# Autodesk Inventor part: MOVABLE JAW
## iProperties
Created: 2006-07
Part Number: MOVABLE JAW
Material: Cast Iron
Document SubType Name: Modeling
Designer: rollin42
Density: 7.25 g/cm^3
Author: rollin42
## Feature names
1. Extrusion1
2. Extrusion2
3. Extrusion3
4. Fillet1
5. Fillet2
6. Hole1
7. Hole2
8. Hole3
9. Rectangular Pattern1
10. Fillet3
